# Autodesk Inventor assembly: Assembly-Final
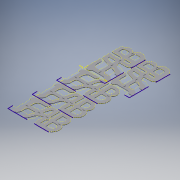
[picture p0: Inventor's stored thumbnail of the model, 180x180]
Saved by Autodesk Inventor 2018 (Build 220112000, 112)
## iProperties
Created: 2018-03
Part Number: Assembly-Final
Document SubType Name: Assembly
Designer: katin
Author: katin
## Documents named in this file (2)
- C:\Users\katin\Documents\FabAcademy2018\+MODEL-FILES\Week 7\+CNC+\Assembly-Final.iam
- C:\Users\katin\Documents\FabAcademy2018\+MODEL-FILES\Week 7\+CNC+\w8-FAB-shelf-holes-1-7.ipt
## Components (5 placed, 1 different names)
1. w8-FAB-shelf-holes-1-7:1 — Flush:1, Flush:2, Flush:3, Flush:4, Flush:7
2. w8-FAB-shelf-holes-1-7:2 — Flush:1, Flush:5, Flush:6
3. w8-FAB-shelf-holes-1-7:3 — Flush:3, Flush:6
4. w8-FAB-shelf-holes-1-7:4 — Flush:4, Flush:5, Flush:7
5. w8-FAB-shelf-holes-1-7:5
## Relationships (7: Flush 7)
- Flush:1: w8-FAB-shelf-holes-1-7:1 ↔ w8-FAB-shelf-holes-1-7:2
- Flush:2: w8-FAB-shelf-holes-1-7:1
- Flush:3: w8-FAB-shelf-holes-1-7:1 ↔ w8-FAB-shelf-holes-1-7:3
- Flush:4: w8-FAB-shelf-holes-1-7:1 ↔ w8-FAB-shelf-holes-1-7:4
- Flush:5: w8-FAB-shelf-holes-1-7:2 ↔ w8-FAB-shelf-holes-1-7:4
- Flush:6: w8-FAB-shelf-holes-1-7:2 ↔ w8-FAB-shelf-holes-1-7:3
- Flush:7: w8-FAB-shelf-holes-1-7:1 ↔ w8-FAB-shelf-holes-1-7:4
